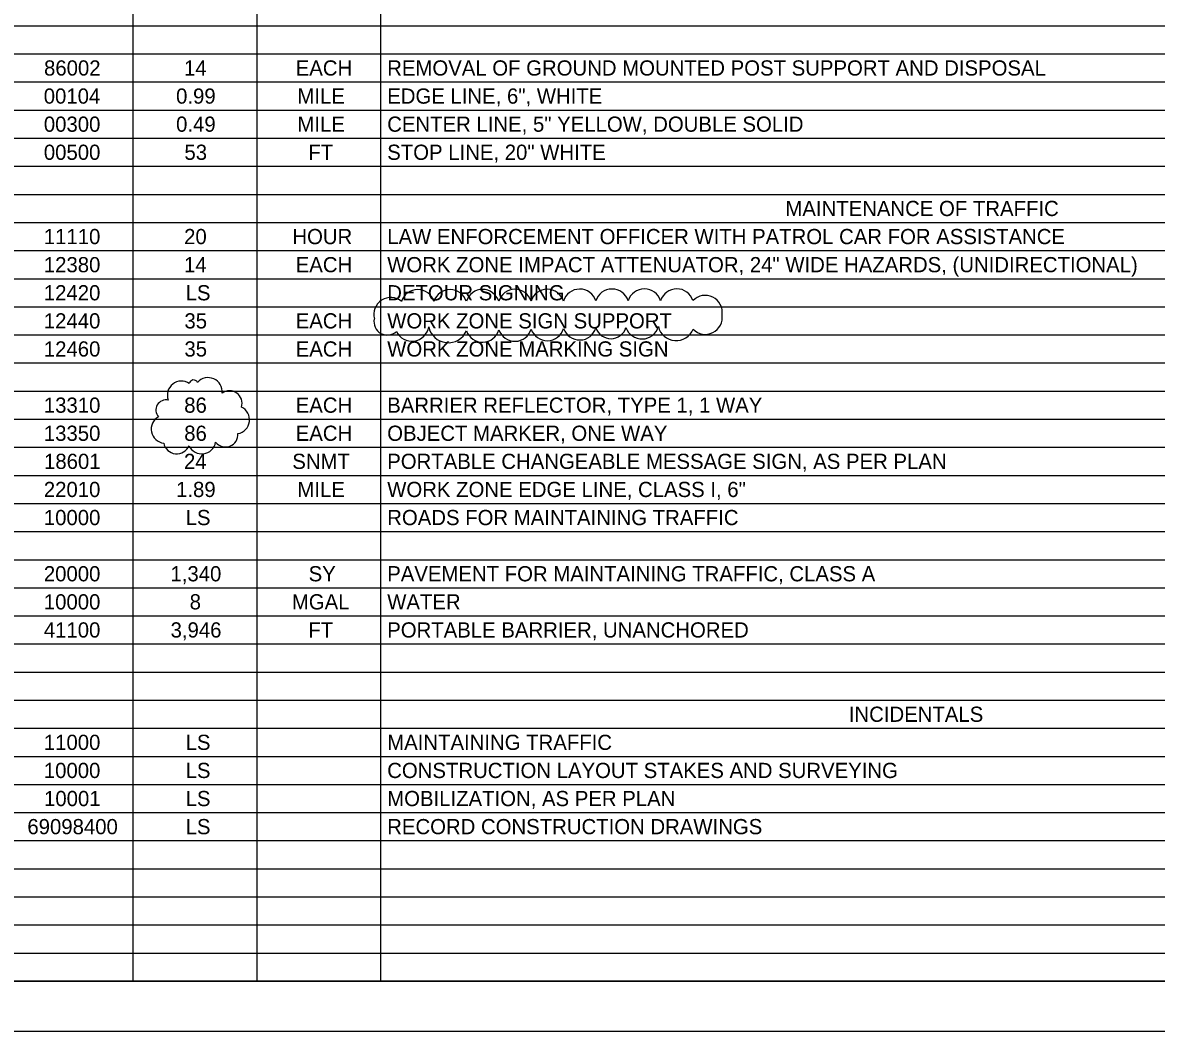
# Model space of a CAD drawing. Extents: x 0 to 36.7, y 0 to 22.
# Drawn here: x 16.94 to 28.24, y 0 to 10.05 of the extents above; entities that cross this region are included whole.
import ezdxf

# ---------------------------------------------------------------- set-up
doc = ezdxf.new("R2010")
doc.units = 0
for name, color, linetype in [('SC_Scratch1', 7, 'Continuous'), ('SH_Border', 7, 'Continuous'), ('SH_Cut_Line', 7, 'Continuous'), ('SH_Text', 7, 'Continuous')]:
    doc.layers.add(name, color=color, linetype=linetype)

msp = doc.modelspace()

# ---------------------------------------------------------------- linework, layer by layer
at = {"layer": 'SC_Scratch1'}
for centre, radius, start, end in [((20.875, 7.222), 0.169, 17.6727, 162.6727), ((21.198, 7.223), 0.169, 17.6727, 162.6727), ((21.521, 7.224), 0.169, 17.6727, 162.6727), ((21.843, 7.225), 0.169, 17.6727, 162.6727), ((22.166, 7.226), 0.169, 17.6721, 162.6721), ((22.489, 7.227), 0.169, 17.6705, 162.6705), ((22.811, 7.228), 0.169, 17.6681, 162.6681), ((23.134, 7.229), 0.169, 17.6638, 162.6638), ((23.457, 7.23), 0.169, 17.6519, 162.6519), ((20.606, 7.143), 0.169, 50.1305, 195.1305), ((23.741, 7.165), 0.169, 351.5461, 136.5461), ((23.741, 7.114), 0.169, 223.9167, 8.9167), ((20.572, 7.071), 0.133, 168.0071, 313.0071), ((20.816, 7.048), 0.171, 205.7457, 350.7457), ((21.179, 7.06), 0.198, 191.3611, 336.3611), ((22.489, 7.058), 0.169, 198.7623, 343.7623), ((22.8, 7.059), 0.157, 197.895, 342.895), ((23.11, 7.068), 0.169, 199.1547, 344.1547), ((23.45, 7.064), 0.182, 193.2751, 338.2751), ((21.52, 7.036), 0.169, 199.2883, 344.2883), ((21.844, 7.045), 0.169, 198.6844, 343.6844), ((22.166, 7.051), 0.169, 198.6222, 343.6222), ((18.52, 6.34), 0.14, 55.6831, 200.6831), ((18.641, 6.448), 0.0429, 24.9246, 169.9246), ((18.786, 6.374), 0.14, 353.8226, 138.8226), ((19, 6.259), 0.124, 342.0242, 127.0242), ((18.367, 6.191), 0.101, 77.2238, 222.2238), ((19.059, 6.094), 0.14, 279.9338, 64.9338), ((18.359, 6), 0.14, 118.7712, 263.7712), ((18.959, 5.948), 0.125, 218.5859, 3.5859), ((18.474, 5.888), 0.133, 191.6548, 336.6548), ((18.723, 5.894), 0.14, 205.0392, 350.0392)]:
    msp.add_arc(centre, radius, start, end, dxfattribs=at)
at = {"layer": 'SH_Border'}
msp.add_lwpolyline([(1.5, 21.5), (33.5, 21.5), (33.5, 0.5), (1.5, 0.5)], close=True, dxfattribs=at)
at = {"layer": 'SH_Cut_Line'}
msp.add_lwpolyline([(0, 0), (34, 0), (34, 22), (0, 22)], close=True, dxfattribs=at)
at = {"layer": 'SH_Text'}
for p, q in [((18.035, 21.5), (18.035, 0.5)), ((19.27, 21.5), (19.27, 0.5)), ((20.505, 21.5), (20.505, 0.5)), ((1.5, 10.02), (32, 10.02)), ((1.5, 9.74), (32, 9.74)), ((1.5, 9.46), (32, 9.46)), ((1.5, 9.18), (32, 9.18)), ((1.5, 8.9), (32, 8.9)), ((1.5, 8.62), (32, 8.62)), ((1.5, 8.34), (32, 8.34)), ((1.5, 8.06), (32, 8.06)), ((1.5, 7.78), (32, 7.78)), ((1.5, 7.5), (32, 7.5)), ((1.5, 7.22), (32, 7.22)), ((1.5, 6.94), (32, 6.94)), ((1.5, 6.66), (32, 6.66)), ((1.5, 6.38), (32, 6.38)), ((1.5, 6.1), (32, 6.1)), ((1.5, 5.82), (32, 5.82)), ((1.5, 5.54), (32, 5.54)), ((1.5, 5.26), (32, 5.26)), ((1.5, 4.98), (32, 4.98)), ((1.5, 4.7), (32, 4.7)), ((1.5, 4.42), (32, 4.42)), ((1.5, 4.14), (32, 4.14)), ((1.5, 3.86), (32, 3.86)), ((1.5, 3.58), (32, 3.58)), ((1.5, 3.3), (32, 3.3)), ((1.5, 3.02), (32, 3.02)), ((1.5, 2.74), (32, 2.74)), ((1.5, 2.46), (32, 2.46)), ((1.5, 2.18), (32, 2.18)), ((1.5, 1.9), (32, 1.9)), ((1.5, 1.62), (32, 1.62)), ((1.5, 1.34), (32, 1.34)), ((1.5, 1.06), (32, 1.06)), ((1.5, 0.78), (32, 0.78)), ((1.5, 0.5), (32, 0.5))]:
    msp.add_line(p, q, dxfattribs=at)

# ---------------------------------------------------------------- texts
for s, height, p in [('86002', 0.1515, (17.151, 9.524)), ('14', 0.1515, (18.546, 9.524)), ('EACH', 0.1515, (19.659, 9.524)), ('REMOVAL OF GROUND MOUNTED POST SUPPORT AND DISPOSAL', 0.15153, (20.571, 9.524)), ('00104', 0.1515, (17.148, 9.244)), ('0.99', 0.1515, (18.467, 9.244)), ('MILE', 0.1515, (19.676, 9.244)), ('EDGE LINE, 6", WHITE', 0.15153, (20.571, 9.244)), ('00300', 0.1515, (17.149, 8.964)), ('0.49', 0.1515, (18.467, 8.964)), ('MILE', 0.1515, (19.676, 8.964)), ('CENTER LINE, 5" YELLOW, DOUBLE SOLID', 0.15153, (20.571, 8.964)), ('00500', 0.1515, (17.149, 8.684)), ('53', 0.1515, (18.55, 8.684)), ('FT', 0.1515, (19.786, 8.684)), ('STOP LINE, 20" WHITE', 0.15153, (20.571, 8.684)), ('MAINTENANCE OF TRAFFIC', 0.15153, (24.539, 8.124)), ('11110', 0.1515, (17.149, 7.844)), ('20', 0.1515, (18.547, 7.844)), ('HOUR', 0.1515, (19.626, 7.844)), ('LAW ENFORCEMENT OFFICER WITH PATROL CAR FOR ASSISTANCE', 0.15153, (20.571, 7.844)), ('12380', 0.1515, (17.149, 7.564)), ('14', 0.1515, (18.546, 7.564)), ('EACH', 0.1515, (19.659, 7.564)), ('WORK ZONE IMPACT ATTENUATOR, 24" WIDE HAZARDS, (UNIDIRECTIONAL)', 0.15153, (20.571, 7.564)), ('12420', 0.1515, (17.149, 7.284)), ('LS', 0.1515, (18.562, 7.284)), ('DETOUR SIGNING', 0.15153, (20.571, 7.284)), ('12440', 0.1515, (17.149, 7.004)), ('35', 0.1515, (18.55, 7.004)), ('EACH', 0.1515, (19.659, 7.004)), ('WORK ZONE SIGN SUPPORT', 0.15153, (20.571, 7.004)), ('12460', 0.1515, (17.149, 6.724)), ('35', 0.1515, (18.55, 6.724)), ('EACH', 0.1515, (19.659, 6.724)), ('WORK ZONE MARKING SIGN', 0.15153, (20.571, 6.724)), ('13310', 0.1515, (17.149, 6.164)), ('86', 0.1515, (18.548, 6.164)), ('EACH', 0.1515, (19.659, 6.164)), ('BARRIER REFLECTOR, TYPE 1, 1 WAY', 0.15153, (20.571, 6.164)), ('13350', 0.1515, (17.149, 5.884)), ('86', 0.1515, (18.548, 5.884)), ('EACH', 0.1515, (19.659, 5.884)), ('OBJECT MARKER, ONE WAY', 0.15153, (20.571, 5.884)), ('18601', 0.1515, (17.151, 5.604)), ('24', 0.1515, (18.546, 5.604)), ('SNMT', 0.1515, (19.625, 5.604)), ('PORTABLE CHANGEABLE MESSAGE SIGN, AS PER PLAN', 0.15153, (20.571, 5.604)), ('22010', 0.1515, (17.149, 5.324)), ('1.89', 0.1515, (18.467, 5.324)), ('MILE', 0.1515, (19.676, 5.324)), ('WORK ZONE EDGE LINE, CLASS I, 6"', 0.15153, (20.571, 5.324)), ('10000', 0.1515, (17.149, 5.044)), ('LS', 0.1515, (18.562, 5.044)), ('ROADS FOR MAINTAINING TRAFFIC', 0.15153, (20.571, 5.044)), ('20000', 0.1515, (17.149, 4.484)), ('1,340', 0.1515, (18.411, 4.484)), ('SY', 0.1515, (19.788, 4.484)), ('PAVEMENT FOR MAINTAINING TRAFFIC, CLASS A', 0.15153, (20.571, 4.484)), ('10000', 0.1515, (17.149, 4.204)), ('8', 0.152, (18.602, 4.204)), ('MGAL', 0.1515, (19.621, 4.204)), ('WATER', 0.1515, (20.571, 4.204)), ('41100', 0.1515, (17.149, 3.924)), ('3,946', 0.1515, (18.412, 3.924)), ('FT', 0.1515, (19.786, 3.924)), ('PORTABLE BARRIER, UNANCHORED', 0.15153, (20.571, 3.924)), ('INCIDENTALS', 0.15153, (25.171, 3.084)), ('11000', 0.1515, (17.149, 2.804)), ('LS', 0.1515, (18.562, 2.804)), ('MAINTAINING TRAFFIC', 0.15153, (20.571, 2.804)), ('10000', 0.1515, (17.149, 2.524)), ('LS', 0.1515, (18.562, 2.524)), ('CONSTRUCTION LAYOUT STAKES AND SURVEYING', 0.15153, (20.571, 2.524)), ('10001', 0.1515, (17.151, 2.244)), ('LS', 0.1515, (18.562, 2.244)), ('MOBILIZATION, AS PER PLAN', 0.15153, (20.571, 2.244)), ('69098400', 0.1515, (16.985, 1.964)), ('LS', 0.1515, (18.562, 1.964)), ('RECORD CONSTRUCTION DRAWINGS', 0.15153, (20.571, 1.964))]:
    msp.add_text(s, height=height, dxfattribs=at).set_placement(p)

doc.saveas('drawing.dxf')
